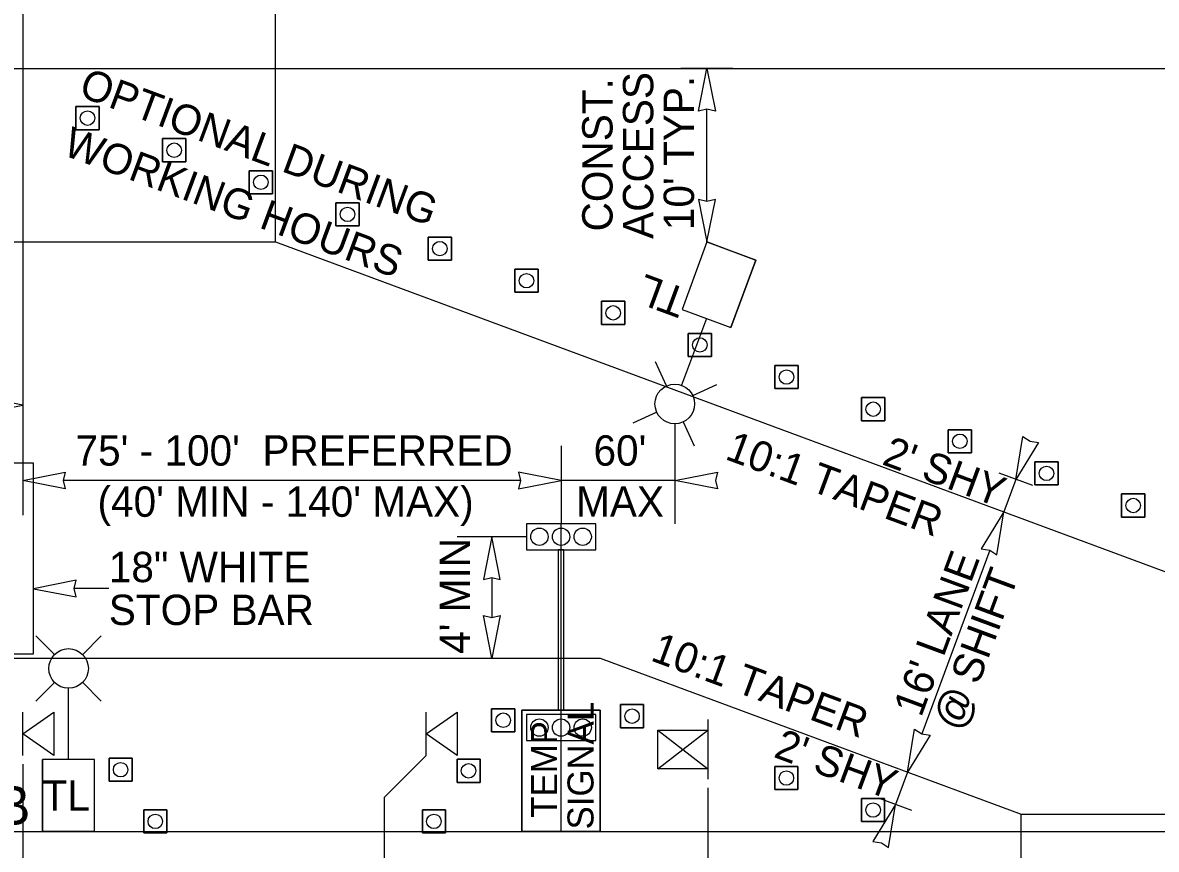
# Model space of a CAD drawing. Extents: x 99976 to 100136, y 99905 to 100011.
# Drawn here: x 100049.858 to 100052.474, y 99916.138 to 99918.045 of the extents above; entities that cross this region are included whole.
import ezdxf

# ---------------------------------------------------------------- set-up
doc = ezdxf.new("R2010")
doc.units = 0
for name, color, linetype in [('RD_ED_ShoulderPavedEdge', 7, 'Continuous'), ('RD_MK_LineEdgeWhite', 7, 'Continuous'), ('TR_WZ_PortableLightStandard', 7, 'Continuous'), ('TR_WZ_PortableSignMount5ftMinBlk-Wht', 7, 'Continuous'), ('TR_WZ_PortableSignMountBlk-Wht', 7, 'Continuous'), ('TR_WZ_TempSignal', 7, 'Continuous'), ('TR_WZ_TrafficCone', 7, 'Continuous'), ('TR_WZ_WorkZoneDetails', 7, 'Continuous'), ('TR_WZ_WorkZoneTextCurrent', 7, 'Continuous')]:
    doc.layers.add(name, color=color, linetype=linetype)

msp = doc.modelspace()

# ---------------------------------------------------------------- linework, layer by layer
at = {"layer": 'RD_ED_ShoulderPavedEdge'}
for p, q in [((100040.1076, 99917.9393), (100055.45, 99917.9393)), ((100040.1076, 99916.1793), (100055.45, 99916.1793))]:
    msp.add_line(p, q, dxfattribs=at)
at = {"layer": 'RD_MK_LineEdgeWhite'}
for p, q in [((100040.1076, 99917.5393), (100050.4406, 99917.5393)), ((100050.4406, 99917.5393), (100052.9246, 99916.6193)), ((100040.1076, 99916.5793), (100051.1899, 99916.5793)), ((100051.1899, 99916.5793), (100052.1619, 99916.2193)), ((100052.1619, 99916.2193), (100055.45, 99916.2193))]:
    msp.add_line(p, q, dxfattribs=at)
at = {"layer": 'TR_WZ_PortableLightStandard'}
for p, q in [((100051.4367, 99917.5393), (100051.3791, 99917.3837)), ((100051.4367, 99917.5393), (100051.3791, 99917.3837)), ((100051.4367, 99917.5393), (100051.5492, 99917.4976)), ((100051.5492, 99917.4976), (100051.4916, 99917.342)), ((100051.4916, 99917.342), (100051.5492, 99917.4976)), ((100051.3791, 99917.3837), (100051.4916, 99917.342)), ((100051.4353, 99917.3628), (100051.3782, 99917.2087)), ((100051.3432, 99917.2073), (100051.3178, 99917.2626)), ((100051.4039, 99917.1848), (100051.4593, 99917.2103)), ((100051.3207, 99917.1467), (100051.2655, 99917.1212)), ((100051.3815, 99917.1242), (100051.4069, 99917.0688)), ((100049.9312, 99916.5878), (100049.8881, 99916.6309)), ((100049.996, 99916.5878), (100050.0389, 99916.6309)), ((100049.9312, 99916.5231), (100049.8881, 99916.48)), ((100049.9636, 99916.3453), (100049.9636, 99916.5097)), ((100049.996, 99916.5231), (100050.0389, 99916.48)), ((100049.9036, 99916.1793), (100049.9036, 99916.3453)), ((100050.0236, 99916.3453), (100049.9036, 99916.3453)), ((100049.9036, 99916.3453), (100049.9036, 99916.1793)), ((100050.0236, 99916.1793), (100050.0236, 99916.3453)), ((100050.0236, 99916.1793), (100050.0236, 99916.3453)), ((100050.0236, 99916.1793), (100049.9036, 99916.1793))]:
    msp.add_line(p, q, dxfattribs=at)
for points in [[(100051.5492, 99917.4976), (100051.493, 99917.5185), (100051.4367, 99917.5393)], [(100051.3791, 99917.3837), (100051.4353, 99917.3628), (100051.4916, 99917.342)], [(100050.0236, 99916.3453), (100049.9636, 99916.3453), (100049.9036, 99916.3453)], [(100049.9036, 99916.1793), (100049.9636, 99916.1793), (100050.0236, 99916.1793)]]:
    msp.add_lwpolyline(points, dxfattribs=at)
for centre in [(100051.3623, 99917.1657), (100051.3623, 99917.1657), (100049.9635, 99916.5555), (100049.9635, 99916.5555)]:
    msp.add_circle(centre, 0.0457, dxfattribs=at)
at = {"layer": 'TR_WZ_PortableSignMount5ftMinBlk-Wht'}
for p, q in [((100051.4384, 99916.4376), (100051.4384, 99916.2997)), ((100051.3233, 99916.3238), (100051.4384, 99916.4134)), ((100051.3233, 99916.4134), (100051.4384, 99916.3238)), ((100051.3807, 99916.3685), (100051.3807, 99916.3685)), ((100051.3808, 99916.3686), (100051.3808, 99916.3686))]:
    msp.add_line(p, q, dxfattribs=at)
msp.add_lwpolyline([(100051.3233, 99916.3238), (100051.3233, 99916.4134), (100051.4384, 99916.4134), (100051.4384, 99916.3238)], close=True, dxfattribs=at)
at = {"layer": 'TR_WZ_PortableSignMountBlk-Wht'}
for p, q in [((100049.8576, 99916.3547), (100049.8576, 99916.4547)), ((100050.7884, 99916.3547), (100050.7884, 99916.4547))]:
    msp.add_line(p, q, dxfattribs=at)
for points in [[(100049.8576, 99916.4046), (100049.9294, 99916.4547), (100049.9294, 99916.3547)], [(100050.7884, 99916.4046), (100050.8602, 99916.4547), (100050.8602, 99916.3547)]]:
    msp.add_lwpolyline(points, close=True, dxfattribs=at)
at = {"layer": 'TR_WZ_TempSignal'}
for p, q in [((100051.02, 99916.8893), (100051.02, 99916.8293)), ((100051.1798, 99916.8893), (100051.02, 99916.8893)), ((100051.0999, 99916.1789), (100051.0999, 99916.8893)), ((100051.1798, 99916.8293), (100051.1798, 99916.8893)), ((100051.02, 99916.8293), (100051.1798, 99916.8293)), ((100051.0932, 99916.8293), (100051.0932, 99916.4591)), ((100051.1065, 99916.8293), (100051.0932, 99916.8293)), ((100051.1065, 99916.4591), (100051.1065, 99916.8293)), ((100051.0098, 99916.1789), (100051.0098, 99916.4591)), ((100051.0098, 99916.4591), (100051.1899, 99916.4591)), ((100051.0932, 99916.4591), (100051.0098, 99916.4591)), ((100051.0098, 99916.4591), (100051.0098, 99916.1789)), ((100051.0932, 99916.4591), (100051.1065, 99916.4591)), ((100051.1065, 99916.4591), (100051.0932, 99916.4591)), ((100051.1899, 99916.4591), (100051.1065, 99916.4591)), ((100051.1899, 99916.4591), (100051.1899, 99916.1789)), ((100051.1899, 99916.1789), (100051.1899, 99916.4591)), ((100051.02, 99916.4491), (100051.02, 99916.3891)), ((100051.1798, 99916.4491), (100051.02, 99916.4491)), ((100051.1798, 99916.3891), (100051.1798, 99916.4491)), ((100051.02, 99916.3891), (100051.1798, 99916.3891)), ((100051.1899, 99916.1789), (100051.0098, 99916.1789)), ((100051.0098, 99916.1789), (100051.1899, 99916.1789))]:
    msp.add_line(p, q, dxfattribs=at)
for points in [[(100051.1798, 99916.8293), (100051.1798, 99916.8893), (100051.02, 99916.8893), (100051.02, 99916.8293), (100051.1798, 99916.8293)], [(100051.1798, 99916.3891), (100051.1798, 99916.4491), (100051.02, 99916.4491), (100051.02, 99916.3891), (100051.1798, 99916.3891)]]:
    msp.add_lwpolyline(points, dxfattribs=at)
for centre in [(100051.0499, 99916.8593), (100051.0499, 99916.8593), (100051.0999, 99916.8593), (100051.0999, 99916.8593), (100051.1498, 99916.8593), (100051.1498, 99916.8593), (100051.0499, 99916.4191), (100051.0499, 99916.4191), (100051.0999, 99916.4191), (100051.0999, 99916.4191), (100051.1498, 99916.4191), (100051.1498, 99916.4191)]:
    msp.add_circle(centre, 0.02, dxfattribs=at)
at = {"layer": 'TR_WZ_TrafficCone'}
for points in [[(100050.0339, 99917.8518), (100049.9805, 99917.8518), (100049.9805, 99917.7984), (100050.0339, 99917.7984), (100050.0339, 99917.8518)], [(100050.0339, 99917.7984), (100049.9805, 99917.7984), (100049.9805, 99917.8518), (100050.0339, 99917.8518), (100050.0339, 99917.7984)], [(100050.2339, 99917.7777), (100050.1805, 99917.7777), (100050.1805, 99917.7244), (100050.2339, 99917.7244), (100050.2339, 99917.7777)], [(100050.2339, 99917.7244), (100050.1805, 99917.7244), (100050.1805, 99917.7777), (100050.2339, 99917.7777), (100050.2339, 99917.7244)], [(100050.4339, 99917.7036), (100050.3805, 99917.7036), (100050.3805, 99917.6503), (100050.4339, 99917.6503), (100050.4339, 99917.7036)], [(100050.4339, 99917.6503), (100050.3805, 99917.6503), (100050.3805, 99917.7036), (100050.4339, 99917.7036), (100050.4339, 99917.6503)], [(100050.6339, 99917.6295), (100050.5805, 99917.6295), (100050.5805, 99917.5762), (100050.6339, 99917.5762), (100050.6339, 99917.6295)], [(100050.6339, 99917.5762), (100050.5805, 99917.5762), (100050.5805, 99917.6295), (100050.6339, 99917.6295), (100050.6339, 99917.5762)], [(100050.8469, 99917.5506), (100050.7936, 99917.5506), (100050.7936, 99917.4973), (100050.8469, 99917.4973), (100050.8469, 99917.5506)], [(100050.8469, 99917.4973), (100050.7936, 99917.4973), (100050.7936, 99917.5506), (100050.8469, 99917.5506), (100050.8469, 99917.4973)], [(100051.0469, 99917.4766), (100050.9936, 99917.4766), (100050.9936, 99917.4232), (100051.0469, 99917.4232), (100051.0469, 99917.4766)], [(100051.0469, 99917.4232), (100050.9936, 99917.4232), (100050.9936, 99917.4766), (100051.0469, 99917.4766), (100051.0469, 99917.4232)], [(100051.2469, 99917.4025), (100051.1936, 99917.4025), (100051.1936, 99917.3492), (100051.2469, 99917.3492), (100051.2469, 99917.4025)], [(100051.2469, 99917.3492), (100051.1936, 99917.3492), (100051.1936, 99917.4025), (100051.2469, 99917.4025), (100051.2469, 99917.3492)], [(100051.4469, 99917.3284), (100051.3936, 99917.3284), (100051.3936, 99917.2751), (100051.4469, 99917.2751), (100051.4469, 99917.3284)], [(100051.4469, 99917.2751), (100051.3936, 99917.2751), (100051.3936, 99917.3284), (100051.4469, 99917.3284), (100051.4469, 99917.2751)], [(100051.6469, 99917.2544), (100051.5936, 99917.2544), (100051.5936, 99917.201), (100051.6469, 99917.201), (100051.6469, 99917.2544)], [(100051.6469, 99917.201), (100051.5936, 99917.201), (100051.5936, 99917.2544), (100051.6469, 99917.2544), (100051.6469, 99917.201)], [(100051.8469, 99917.1803), (100051.7936, 99917.1803), (100051.7936, 99917.1269), (100051.8469, 99917.1269), (100051.8469, 99917.1803)], [(100051.8469, 99917.1269), (100051.7936, 99917.1269), (100051.7936, 99917.1803), (100051.8469, 99917.1803), (100051.8469, 99917.1269)], [(100052.0469, 99917.1062), (100051.9936, 99917.1062), (100051.9936, 99917.0529), (100052.0469, 99917.0529), (100052.0469, 99917.1062)], [(100052.0469, 99917.0529), (100051.9936, 99917.0529), (100051.9936, 99917.1062), (100052.0469, 99917.1062), (100052.0469, 99917.0529)], [(100052.2469, 99917.0321), (100052.1936, 99917.0321), (100052.1936, 99916.9788), (100052.2469, 99916.9788), (100052.2469, 99917.0321)], [(100052.2469, 99916.9788), (100052.1936, 99916.9788), (100052.1936, 99917.0321), (100052.2469, 99917.0321), (100052.2469, 99916.9788)], [(100052.4469, 99916.9581), (100052.3936, 99916.9581), (100052.3936, 99916.9047), (100052.4469, 99916.9047), (100052.4469, 99916.9581)], [(100052.4469, 99916.9047), (100052.3936, 99916.9047), (100052.3936, 99916.9581), (100052.4469, 99916.9581), (100052.4469, 99916.9047)], [(100050.9931, 99916.4626), (100050.9398, 99916.4626), (100050.9398, 99916.4093), (100050.9931, 99916.4093), (100050.9931, 99916.4626)], [(100050.9931, 99916.4093), (100050.9398, 99916.4093), (100050.9398, 99916.4626), (100050.9931, 99916.4626), (100050.9931, 99916.4093)], [(100051.237, 99916.472), (100051.2903, 99916.472), (100051.2903, 99916.4187), (100051.237, 99916.4187), (100051.237, 99916.472)], [(100051.237, 99916.4187), (100051.2903, 99916.4187), (100051.2903, 99916.472), (100051.237, 99916.472), (100051.237, 99916.4187)], [(100050.1101, 99916.3486), (100050.0568, 99916.3486), (100050.0568, 99916.2953), (100050.1101, 99916.2953), (100050.1101, 99916.3486)], [(100050.1101, 99916.2953), (100050.0568, 99916.2953), (100050.0568, 99916.3486), (100050.1101, 99916.3486), (100050.1101, 99916.2953)], [(100050.8599, 99916.346), (100050.9132, 99916.346), (100050.9132, 99916.2926), (100050.8599, 99916.2926), (100050.8599, 99916.346)], [(100050.8599, 99916.2926), (100050.9132, 99916.2926), (100050.9132, 99916.346), (100050.8599, 99916.346), (100050.8599, 99916.2926)], [(100051.5933, 99916.3294), (100051.6466, 99916.3294), (100051.6466, 99916.2761), (100051.5933, 99916.2761), (100051.5933, 99916.3294)], [(100051.5933, 99916.2761), (100051.6466, 99916.2761), (100051.6466, 99916.3294), (100051.5933, 99916.3294), (100051.5933, 99916.2761)], [(100051.7933, 99916.2553), (100051.8466, 99916.2553), (100051.8466, 99916.202), (100051.7933, 99916.202), (100051.7933, 99916.2553)], [(100051.7933, 99916.202), (100051.8466, 99916.202), (100051.8466, 99916.2553), (100051.7933, 99916.2553), (100051.7933, 99916.202)], [(100050.1901, 99916.2293), (100050.1368, 99916.2293), (100050.1368, 99916.176), (100050.1901, 99916.176), (100050.1901, 99916.2293)], [(100050.1901, 99916.176), (100050.1368, 99916.176), (100050.1368, 99916.2293), (100050.1901, 99916.2293), (100050.1901, 99916.176)], [(100050.7799, 99916.2293), (100050.8332, 99916.2293), (100050.8332, 99916.176), (100050.7799, 99916.176), (100050.7799, 99916.2293)], [(100050.7799, 99916.176), (100050.8332, 99916.176), (100050.8332, 99916.2293), (100050.7799, 99916.2293), (100050.7799, 99916.176)]]:
    msp.add_lwpolyline(points, dxfattribs=at)
for centre in [(100050.0072, 99917.8251), (100050.2072, 99917.751), (100050.4072, 99917.677), (100050.6072, 99917.6029), (100050.8202, 99917.524), (100051.0202, 99917.4499), (100051.2202, 99917.3758), (100051.4202, 99917.3018), (100051.6202, 99917.2277), (100051.8202, 99917.1536), (100052.0202, 99917.0795), (100052.2202, 99917.0055), (100052.4202, 99916.9314), (100051.2637, 99916.4453), (100050.9665, 99916.436), (100050.0835, 99916.3219), (100050.8865, 99916.3193), (100051.62, 99916.3027), (100051.82, 99916.2287), (100050.1635, 99916.2026), (100050.8065, 99916.2026)]:
    msp.add_circle(centre, 0.0167, dxfattribs=at)
at = {"layer": 'TR_WZ_WorkZoneDetails'}
for p, q in [((100049.8576, 99918.2793), (100049.8576, 99916.9093)), ((100050.4406, 99917.5393), (100050.4406, 99918.2793)), ((100051.4967, 99917.9393), (100051.3767, 99917.9393)), ((100051.4367, 99917.633), (100051.4367, 99917.8456)), ((100051.3623, 99917.12), (100051.3623, 99916.8893)), ((100051.0999, 99917.0693), (100051.0999, 99916.8893)), ((100052.1883, 99916.9773), (100052.1111, 99917.0059)), ((100051.0061, 99916.9893), (100049.9513, 99916.9893)), ((100051.3623, 99916.9893), (100051.0999, 99916.9893)), ((100052.1497, 99916.9916), (100052.1219, 99916.9166)), ((100051.02, 99916.8593), (100050.86, 99916.8593)), ((100052.0894, 99916.8287), (100051.9322, 99916.4043)), ((100050.94, 99916.7656), (100050.94, 99916.673)), ((100050.0563, 99916.7401), (100049.9763, 99916.7401)), ((100050.7884, 99916.3547), (100050.6914, 99916.2577)), ((100049.8576, 99916.3347), (100049.8576, 99915.8393)), ((100051.8996, 99916.3164), (100051.8718, 99916.2414)), ((100051.4384, 99916.2797), (100051.4384, 99915.8393)), ((100050.6914, 99916.2577), (100050.6914, 99915.8393)), ((100051.9094, 99916.2275), (100051.8322, 99916.2561)), ((100052.1619, 99915.8393), (100052.1619, 99916.2193))]:
    msp.add_line(p, q, dxfattribs=at)
for points in [[(100051.4367, 99917.9393), (100051.456, 99917.841), (100051.4367, 99917.8456), (100051.4174, 99917.841)], [(100051.4367, 99917.5393), (100051.456, 99917.6376), (100051.4367, 99917.633), (100051.4174, 99917.6376)], [(100049.8576, 99917.1626), (100049.7593, 99917.1819), (100049.7638, 99917.1626), (100049.7593, 99917.1434)], [(100052.1497, 99916.9916), (100052.1658, 99917.0905), (100052.1822, 99917.0795), (100052.2019, 99917.0771)], [(100049.8576, 99916.9893), (100049.9558, 99917.0085), (100049.9513, 99916.9893), (100049.9558, 99916.97)], [(100051.0999, 99916.9893), (100051.0016, 99917.0085), (100051.0061, 99916.9893), (100051.0016, 99916.97)], [(100051.3623, 99916.9893), (100051.4606, 99917.0085), (100051.4561, 99916.9893), (100051.4606, 99916.97)], [(100052.1219, 99916.9166), (100052.0697, 99916.8311), (100052.0894, 99916.8287), (100052.1058, 99916.8177)], [(100050.94, 99916.8593), (100050.9207, 99916.761), (100050.94, 99916.7656), (100050.9593, 99916.761)], [(100049.8826, 99916.7393), (100049.981, 99916.7209), (100049.9763, 99916.7401), (100049.9807, 99916.7594)], [(100050.94, 99916.5793), (100050.9207, 99916.6776), (100050.94, 99916.673), (100050.9593, 99916.6776)], [(100051.8996, 99916.3164), (100051.9157, 99916.4153), (100051.9322, 99916.4043), (100051.9518, 99916.4019)], [(100051.8718, 99916.2414), (100051.8196, 99916.156), (100051.8393, 99916.1535), (100051.8558, 99916.1426)]]:
    msp.add_lwpolyline(points, close=True, dxfattribs=at)
msp.add_lwpolyline([(100049.8326, 99916.5893), (100049.8826, 99916.5893), (100049.8826, 99917.0293), (100049.8326, 99917.0293), (100049.8326, 99916.5893)], dxfattribs=at)
msp.add_lwpolyline([(100049.8326, 99916.5893), (100049.8826, 99916.5893), (100049.8826, 99917.0293), (100049.8326, 99917.0293), (100049.8326, 99916.5893)], dxfattribs=at)

# ---------------------------------------------------------------- texts
at = {"layer": 'TR_WZ_PortableLightStandard'}
msp.add_text('TL', height=0.07, rotation=159.6769, dxfattribs=at).set_placement((100051.3958, 99917.4287))
msp.add_text('TL', height=0.07, dxfattribs=at).set_placement((100049.9034, 99916.2273))
at = {"layer": 'TR_WZ_TempSignal'}
for s, p in [('SIGNAL', (100051.1748, 99916.184)), ('TEMP', (100051.0908, 99916.2111))]:
    msp.add_text(s, height=0.06, rotation=90, dxfattribs=at).set_placement(p)
msp.add_text('PB', height=0.09, dxfattribs=at).set_placement((100049.7148, 99916.1943))
at = {"layer": 'TR_WZ_WorkZoneTextCurrent'}
for s, rotation, p in [('OPTIONAL DURING', 339.6769, (100049.984, 99917.8768)), ('ACCESS', 90, (100051.3127, 99917.5465)), ('CONST.', 90, (100051.2187, 99917.5637)), ("10' TYP.", 90, (100051.4067, 99917.5666)), ('WORKING HOURS', 339.6769, (100049.9472, 99917.7411)), ("75' - 100'  PREFERRED", 360, (100049.9795, 99917.0233)), ("60'", 360, (100051.1748, 99917.0233)), ('10:1 TAPER', 339.6769, (100051.4758, 99917.0392)), ("2' SHY", 339.6769, (100051.838, 99917.0271)), ("(40' MIN - 140' MAX)", 360, (100050.0303, 99916.9053)), ('MAX', 360, (100051.1346, 99916.9053)), ("4' MIN", 90, (100050.89, 99916.5891)), ("16' LANE", 69.6769, (100051.9308, 99916.4408)), ('SHIFT', 69.6769, (100052.063, 99916.5156)), ('10:1 TAPER', 339.6769, (100051.3038, 99916.5747)), ('@', 69.6769, (100052.023, 99916.4077)), ("2' SHY", 339.6769, (100051.5879, 99916.3519))]:
    msp.add_text(s, height=0.07, rotation=rotation, dxfattribs=at).set_placement(p)
for s, p in [('18" WHITE', (100050.0563, 99916.7545)), ('STOP BAR', (100050.0563, 99916.6557))]:
    msp.add_text(s, height=0.07, dxfattribs=at).set_placement(p)

doc.saveas('drawing.dxf')
